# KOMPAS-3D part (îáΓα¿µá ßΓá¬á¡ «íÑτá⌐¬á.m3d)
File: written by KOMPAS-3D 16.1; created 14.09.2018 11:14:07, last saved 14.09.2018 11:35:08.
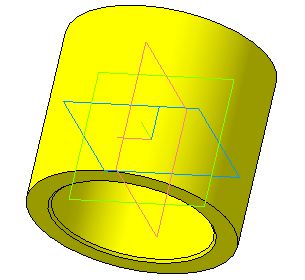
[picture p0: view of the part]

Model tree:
1. Эскиз:1
2. Операция выдавливания:1
     Расстояние 1 = 65
3. Фаска:1  (labels: Полипропилен  ГОСТ 26996-86)
     Угол = 45; Длина 1 = 1; Длина 2 = 1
